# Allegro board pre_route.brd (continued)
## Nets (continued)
DIFF_RX_DRSTAT_N0: J109.10H U7.AH14
DIFF_RX_DRSTAT_N1: J109.9H U7.AH13
DIFF_RX_DRSTAT_P0: J109.10G U7.AG16
DIFF_RX_DRSTAT_P1: J109.9G U7.AH5
DIFF_RX_N<0>: J57.A1 J108.10D U7.Y31
DIFF_RX_N<1>: J57.A2 J108.9H U7.Y29
DIFF_RX_N<2>: J57.A4 J108.9D U7.W32
DIFF_RX_N<3>: J57.A5 J108.10F U7.V31
DIFF_RX_N<4>: J57.A7 J108.10B U7.AJ32
DIFF_RX_N<5>: J57.A8 J108.9F U7.AH32
DIFF_RX_N<6>: J57.A10 J108.8F U7.AH30
DIFF_RX_N<7>: J57.A11 J108.8D U7.AG32
DIFF_RX_N<8>: J57.A15 J108.7F U7.AG30
DIFF_RX_N<9>: J57.A16 J108.8B U7.AF32
DIFF_RX_N<10>: J57.A18 J108.7B U7.AF30
DIFF_RX_N<11>: J57.A19 J108.7H U7.AE32
DIFF_RX_N<12>: J57.A21 J108.6B U7.AE30
DIFF_RX_N<13>: J57.A22 J108.6D U7.AD32
DIFF_RX_N<14>: J57.A24 J108.7D U7.AC32
DIFF_RX_N<15>: J57.A25 J108.6H U7.AB32
DIFF_RX_P<0>: J57.B1 J108.10C U7.Y30
DIFF_RX_P<1>: J57.B2 J108.9G U7.Y28
DIFF_RX_P<2>: J57.B4 J108.9C U7.W31
DIFF_RX_P<3>: J57.B5 J108.10E U7.V30
DIFF_RX_P<4>: J57.B7 J108.10A U7.AJ31
DIFF_RX_P<5>: J57.B8 J108.9E U7.AH31
DIFF_RX_P<6>: J57.B10 J108.8E U7.AH29
DIFF_RX_P<7>: J57.B11 J108.8C U7.AG31
DIFF_RX_P<8>: J57.B15 J108.7E U7.AG29
DIFF_RX_P<9>: J57.B16 J108.8A U7.AF31
DIFF_RX_P<10>: J57.B18 J108.7A U7.AF29
DIFF_RX_P<11>: J57.B19 J108.7G U7.AE31
DIFF_RX_P<12>: J57.B21 J108.6A U7.AE29
DIFF_RX_P<13>: J57.B22 J108.6C U7.AD31
DIFF_RX_P<14>: J57.B24 J108.7C U7.AC31
DIFF_RX_P<15>: J57.B25 J108.6G U7.AB31
DIFF_RX_RCTL_N: J108.6F U7.AB30
DIFF_RX_RCTL_P: J108.6E U7.AB29
DIFF_RX_RDCLK_N: J57.A13 J108.9B R61.1
DIFF_RX_RDCLK_P: J57.B13 J108.9A R61.2
DIFF_RX_RSCLK: J108.8G U7.AM8
DIFF_RX_RSTAT<0>: J108.10H U7.AM7
DIFF_RX_RSTAT<1>: J108.10G U7.AM6
DIFF_TX_DTSCLK_N: J109.5B
DIFF_TX_DTSCLK_P: J109.5A
DIFF_TX_DTSTAT_N0: J109.2D U7.Y11
DIFF_TX_DTSTAT_N1: J109.1D U7.AB12
DIFF_TX_DTSTAT_P0: J109.2C U7.Y10
DIFF_TX_DTSTAT_P1: J109.1C U7.AD10
DIFF_TX_N<0>: J58.A1 J108.2H U7.T28
DIFF_TX_N<1>: J58.A2 J108.1D U7.T23
DIFF_TX_N<2>: J58.A4 J108.1B U7.R29
DIFF_TX_N<3>: J58.A5 J108.1F U7.R27
DIFF_TX_N<4>: J58.A7 J108.3F U7.R25
DIFF_TX_N<5>: J58.A8 J108.1H U7.R23
DIFF_TX_N<6>: J58.A10 J108.3B U7.P29
DIFF_TX_N<7>: J58.A11 J108.2B U7.P27
DIFF_TX_N<8>: J58.A15 J108.4H U7.N27
DIFF_TX_N<9>: J58.A16 J108.2F U7.N25
DIFF_TX_N<10>: J58.A18 J108.4B U7.N23
DIFF_TX_N<11>: J58.A19 J108.4D U7.M27
DIFF_TX_N<12>: J58.A21 J108.4F U7.M25
DIFF_TX_N<13>: J58.A22 J108.5F U7.M23
DIFF_TX_N<14>: J58.A24 J108.3D U7.L26
DIFF_TX_N<15>: J58.A25 J108.5H U7.L24
DIFF_TX_P<0>: J58.B1 J108.2G U7.T27
DIFF_TX_P<1>: J58.B2 J108.1C U7.T22
DIFF_TX_P<2>: J58.B4 J108.1A U7.R28
DIFF_TX_P<3>: J58.B5 J108.1E U7.R26
DIFF_TX_P<4>: J58.B7 J108.3E U7.R24
DIFF_TX_P<5>: J58.B8 J108.1G U7.R22
DIFF_TX_P<6>: J58.B10 J108.3A U7.P28
DIFF_TX_P<7>: J58.B11 J108.2A U7.P26
DIFF_TX_P<8>: J58.B15 J108.4G U7.N26
DIFF_TX_P<9>: J58.B16 J108.2E U7.N24
DIFF_TX_P<10>: J58.B18 J108.4A U7.N22
DIFF_TX_P<11>: J58.B19 J108.4C U7.M26
DIFF_TX_P<12>: J58.B21 J108.4E U7.M24
DIFF_TX_P<13>: J58.B22 J108.5E U7.M22
DIFF_TX_P<14>: J58.B24 J108.3C U7.L25
DIFF_TX_P<15>: J58.B25 J108.5G U7.L23
DIFF_TX_TCTL_N: J108.5D U7.K27
DIFF_TX_TCTL_P: J108.5C U7.K26
DIFF_TX_TDCLK_N: J58.A13 J108.3H U7.P25
DIFF_TX_TDCLK_P: J58.B13 J108.3G U7.P24
DIFF_TX_TSCLK: J108.5A U7.AM9
DIFF_TX_TSTAT<0>: J108.2D U7.AE13
DIFF_TX_TSTAT<1>: J108.2C U7.AB13
DIMM_ODT0: XU2.195
DIVIDE_BY_20_LVPECL_OUT_N: J37.1(OUTPUT) R40.2 R43.1 U6.12(_FWSL_Q3)
DIVIDE_BY_20_LVPECL_OUT_P: J43.1(OUTPUT) R43.2 R48.1 U6.13
DIVIDE_BY_20_LVTTL_OUT: J49.1(OUTPUT) R52.2
DL: U14.6 U17.4
DPA_RX_N<0>: J89.1(OUTPUT) U7.R31
DPA_RX_N<1>: J100.1(OUTPUT) U7.P32
DPA_RX_P<0>: J84.1(OUTPUT) U7.R30
DPA_RX_P<1>: J95.1(OUTPUT) U7.P31
DPA_TX_N<0>: J94.1(OUTPUT) U7.Y27
DPA_TX_N<1>: J102.1(OUTPUT) U7.Y23
DPA_TX_P<0>: J99.1(OUTPUT) U7.Y26
DPA_TX_P<1>: J106.1(OUTPUT) U7.Y22
DPACLK_IN_N: J107.1(OUTPUT)
DPACLK_IN_P: J103.1(OUTPUT)
DPACLK_OUT_N: J88.1(OUTPUT) U7.Y25
DPACLK_OUT_P: J83.1(OUTPUT) U7.Y24
EN_CONFIG_DEV_N: R145.1 U19.29 U20.39 U21.29
EN_PS_MODE_N: R51.1 U19.39
EPC16_TDI: U29.42
EXT_CLK1: J104.1(OUTPUT) R176.2 U32.4
EXT_CLK2: J91.1(OUTPUT) R177.2 U18.4
EXT_CLK_IN_N: J62.1(OUTPUT) R86.2 U10.4
EXT_CLK_IN_P: J61.1(OUTPUT) R86.1 U10.3
FLASH_A<0>: U15.AD31 U29.65 U29.75 U31.25
FLASH_A<1>: U15.AD32 U29.56 U29.62 U31.24
FLASH_A<2>: U15.AC31 U29.55 U31.23
FLASH_A<3>: U15.AB32 U29.54 U31.22
FLASH_A<4>: U15.AB26 U29.53 U31.21
FLASH_A<5>: U15.AA24 U29.52 U31.20
FLASH_A<6>: U15.AG29 U29.51 U31.19
FLASH_A<7>: U15.AG30 U29.50 U31.18
FLASH_A<8>: U15.AG32 U29.34 U31.8
FLASH_A<9>: U15.AG31 U29.32 U31.7
FLASH_A<10>: U15.AF29 U29.31 U31.6
FLASH_A<11>: U15.AF30 U29.29 U31.5
FLASH_A<12>: U15.AF31 U29.28 U31.4
FLASH_A<13>: U15.AF32 U29.27 U31.3
FLASH_A<14>: U15.AE29 U29.26 U31.2
FLASH_A<15>: U15.AE30 U29.21 U29.25 U31.1
FLASH_A<16>: U15.AE31 U29.6 U29.17 U31.48
FLASH_A<17>: U15.AE32 U29.49 U31.17
FLASH_A<18>: U15.AD29 U29.47 U31.16
FLASH_A<19>: U15.AD30 U29.46 U31.9
FLASH_A<20>: U15.AC30 U29.36 U31.10
FLASH_A<21>: U15.AC29 U31.13
FLASH_BYTEN: R233.1 U15.Y24 U31.47
FLASH_CEN: R231.1 U15.AA26 U31.26
FLASH_D<0>: U15.AF25 U29.81 U31.29
FLASH_D<1>: U15.AF26 U29.83 U31.31
FLASH_D<2>: U15.AF28 U29.86 U31.33
FLASH_D<3>: U15.AF27 U29.89 U31.35
FLASH_D<4>: U15.AE26 U29.93 U31.38
FLASH_D<5>: U15.AE25 U29.95 U31.40
FLASH_D<6>: U15.AE27 U29.98 U31.42
FLASH_D<7>: U15.AE28 U29.100 U31.44
FLASH_D<8>: U15.AD25 U29.82 U31.30
FLASH_D<9>: U15.AD26 U29.85 U31.32
FLASH_D<10>: U15.AD27 U29.87 U31.34
FLASH_D<11>: U15.AD28 U29.90 U31.36
FLASH_D<12>: U15.AC28 U29.94 U31.39
FLASH_D<13>: U15.AC27 U29.97 U31.41
FLASH_D<14>: U15.AC26 U29.99 U31.43
FLASH_D<15>: U15.AC25 U29.1 U31.45
FLASH_OEN: R232.1 U15.AB27 U31.28
FLASH_RDY_BSYN: R360.2 U31.15
FLASH_RESETN: R280.1 U15.AA25 U31.12
FLASH_WEN: R281.1 U15.AA27 U31.11
FLASH_WPN: R279.1 U31.14(WP_ACC)
GLOBAL_RST_LED: RN22.3 U34.19
GLOBAL_RST_N: R149.1 RN20.14 U19.26 U19.36 U21.26 U34.30 U43.15
GLOBAL_RST_N_IN: C657.1 R149.2 R175.1 U43.1
GX_A_A: RN36.1 U25.12
GX_A_B: RN35.1 U25.23
GX_ALERTN: U5.11 U15.L14
GX_B_A: RN36.2 U25.11
GX_B_B: RN35.2 U25.22
GX_C_A: RN36.3 U25.9
GX_C_B: RN35.3 U25.20
GX_CDONE_BUF_N: R144.1 R179.1 U19.37 U21.27
GX_CDONE_N: U19.3
GX_CONFIG_BUF_N: R42.1
GX_D_A: RN36.4 U25.8
GX_D_B: RN35.4 U25.19
GX_DATA0: U19.34 U21.24
GX_DATA1: U21.23
GX_DATA2: U21.22
GX_DATA3: U21.21
GX_DATA4: U20.34
GX_DATA5: U20.33
GX_DATA6: U20.32
GX_DATA7: U20.31
GX_DCLK_BUF: R142.1 U21.28
GX_DEV_CLR_LED: RN22.1 U34.22
GX_DIG_1_A: RN15.16 U7.AJ8 U25.37
GX_DIG_1_B: RN15.15 U7.AK10 U25.38
GX_DIG_1_C: RN15.14 U7.AK11 U25.40
GX_DIG_1_D: RN15.13 U7.AK12 U25.41
GX_DIG_1_DP: RN15.9(2) U7.AK6 U25.47
GX_DIG_1_E: RN15.12 U7.AK13 U25.43
GX_DIG_1_F: RN15.11 U7.AK4 U25.44
GX_DIG_1_G: RN15.10 U7.AK5 U25.46
GX_DIG_2_A: RN16.16 U7.AJ10 U25.26
GX_DIG_2_B: RN16.15 U7.AJ11 U25.27
GX_DIG_2_C: RN16.14 U7.AJ12 U25.29
GX_DIG_2_D: RN16.13 U7.AJ13 U25.30
GX_DIG_2_DP: RN16.9(2) U7.AJ7 U25.36
GX_DIG_2_E: RN16.12 U7.AJ14 U25.32
GX_DIG_2_F: RN16.11 U7.AJ5 U25.33
GX_DIG_2_G: RN16.10 U7.AJ6 U25.35
GX_DIP<0>: RN37.14 U7.AJ21
GX_DIP<1>: RN37.13 U7.AJ20
GX_DIP<2>: RN37.12 U7.AJ19
GX_DIP<3>: RN37.11 U7.AH28
GX_DIP<4>: RN37.9(2) U7.AH26
GX_DIP<5>: RN38.15 U7.AH25
GX_DIP<6>: RN38.13 U7.AH24
GX_DIP<7>: RN38.11 U7.AH22
GX_DP_A: RN36.8 U25.2
GX_DP_B: RN35.8 U25.13
GX_E_A: RN36.5 U25.6
GX_E_B: RN35.5 U25.17
GX_EPC16_CEN: U15.AE13 U30.78
GX_EPC16_OEN: U15.AC13 U30.80
GX_EPC16_RPN: U15.AG12 U30.39 U30.72
GX_EPC16_WEN: U15.AD13 U30.33 U30.38
GX_F_A: RN36.6 U25.5
GX_F_B: RN35.6 U25.16
GX_FLASH_A<0>: U15.AK4 U30.65 U30.75
GX_FLASH_A<1>: U15.AK3 U30.56 U30.62
GX_FLASH_A<2>: U15.AH5 U30.55
GX_FLASH_A<3>: U15.AJ5 U30.54
GX_FLASH_A<4>: U15.AJ4 U30.53
GX_FLASH_A<5>: U15.AM4 U30.52
GX_FLASH_A<6>: U15.AL4 U30.51
GX_FLASH_A<7>: U15.AL3 U30.50
GX_FLASH_A<8>: U15.AJ6 U30.34
GX_FLASH_A<9>: U15.AK6 U30.32
GX_FLASH_A<10>: U15.AL5 U30.31
GX_FLASH_A<11>: U15.AK7 U30.29
GX_FLASH_A<12>: U15.AM5 U30.28
GX_FLASH_A<13>: U15.AJ7 U30.27
GX_FLASH_A<14>: U15.AM6 U30.26
GX_FLASH_A<15>: U15.AL6 U30.21 U30.25
GX_FLASH_A<16>: U15.AL7 U30.6 U30.17
GX_FLASH_A<17>: U15.AJ8 U30.49
GX_FLASH_A<18>: U15.AM7 U30.47
GX_FLASH_A<19>: U15.AH9 U30.46
GX_FLASH_A<20>: U15.AM8 U30.36
GX_FLASH_D<0>: U15.AE12 U30.81
GX_FLASH_D<1>: U15.AC12 U30.83
GX_FLASH_D<2>: U15.AA12 U30.86
GX_FLASH_D<3>: U15.AD12 U30.89
GX_FLASH_D<4>: U15.AB11 U30.93
GX_FLASH_D<5>: U15.AE11 U30.95
GX_FLASH_D<6>: U15.AF10 U30.98
GX_FLASH_D<7>: U15.AG10 U30.100
GX_FLASH_D<8>: U15.AG11 U30.82
GX_FLASH_D<9>: U15.AD9 U30.85
GX_FLASH_D<10>: U15.AG9 U30.87
GX_FLASH_D<11>: U15.AC9 U30.90
GX_FLASH_D<12>: U15.AE9 U30.94
GX_FLASH_D<13>: U15.AF9 U30.97
GX_FLASH_D<14>: U15.AD14 U30.99
GX_FLASH_D<15>: U15.AB13 U30.1
GX_G_A: RN36.7 U25.3
GX_G_B: RN35.7 U25.14
GX_HEADER<0>: J53.1 U7.AM5
GX_HEADER<1>: J53.3 U7.AM4
GX_HEADER<2>: J53.5 U7.AM14
GX_HEADER<3>: J53.7 U7.AM12
GX_HEADER<4>: J53.9 U7.AM11
GX_HEADER<5>: J53.11 U7.AM10
GX_HEADER<6>: J53.13 U7.AL9
GX_HEADER<7>: J53.15 U7.AL8
GX_HEADER<8>: J53.17 U7.AL7
GX_HEADER<9>: J53.19 U7.AL6
GX_HEADER<10>: J53.20 U7.AL5
GX_HEADER<11>: J53.18 U7.AL4
GX_HEADER<12>: J53.16 U7.AL14
GX_HEADER<13>: J53.14 U7.AL13
GX_HEADER<14>: J53.12 U7.AL12
GX_HEADER<15>: J53.10 U7.AL11
GX_HEADER<16>: J53.8 U7.AL10
GX_HEADER<17>: J53.6 U7.AK9
GX_HEADER<18>: J53.4 U7.AK8
GX_HEADER<19>: J53.2 U7.AK7
GX_LED<0>: RN19.15 U7.AC16 U34.38
GX_LED<1>: RN19.16 U7.AC15 U34.37
GX_LED<2>: RN20.10 U7.AC14 U34.36
GX_LED<3>: RN20.11 U7.AC12 U34.35
GX_LED<4>: RN20.12 U7.AB16 U34.33
GX_LED<5>: RN20.13 U7.AB14 U34.32
GX_MICTOR_EP_<0>: J34.37 U7.AM28
GX_MICTOR_EP_<1>: J34.35 U7.AM27
GX_MICTOR_EP_<2>: J34.33 U7.AM26
GX_MICTOR_EP_<3>: J34.31 U7.AM25
GX_MICTOR_EP_<4>: J34.29 U7.AM24
GX_MICTOR_EP_<5>: J34.27 U7.AM23
GX_MICTOR_EP_<6>: J34.25 U7.AM22
GX_MICTOR_EP_<7>: J34.23 U7.AM21
GX_MICTOR_EP_<8>: J34.21 U7.AL29
GX_MICTOR_EP_<9>: J34.19 U7.AL28
GX_MICTOR_EP_<10>: J34.17 U7.AL27
GX_MICTOR_EP_<11>: J34.15 U7.AL26
GX_MICTOR_EP_<12>: J34.13 U7.AL25
GX_MICTOR_EP_<13>: J34.11 U7.AL24
GX_MICTOR_EP_<14>: J34.9 U7.AL23
GX_MICTOR_EP_<15>: J34.7 U7.AL22
GX_MICTOR_EP_CLK: J34.5 U7.AM29
GX_MICTOR_OP_<0>: J34.38 U7.AL20
GX_MICTOR_OP_<1>: J34.36 U7.AK29
GX_MICTOR_OP_<2>: J34.34 U7.AK28
GX_MICTOR_OP_<3>: J34.32 U7.AK27
GX_MICTOR_OP_<4>: J34.30 U7.AK26
GX_MICTOR_OP_<5>: J34.28 U7.AK25
GX_MICTOR_OP_<6>: J34.26 U7.AK24
GX_MICTOR_OP_<7>: J34.24 U7.AK23
GX_MICTOR_OP_<8>: J34.22 U7.AK22
GX_MICTOR_OP_<9>: J34.20 U7.AK21
GX_MICTOR_OP_<10>: J34.18 U7.AK20
GX_MICTOR_OP_<11>: J34.16 U7.AJ28
GX_MICTOR_OP_<12>: J34.14 U7.AJ27
GX_MICTOR_OP_<13>: J34.12 U7.AJ26
GX_MICTOR_OP_<14>: J34.10 U7.AJ25
GX_MICTOR_OP_<15>: J34.8 U7.AJ23
GX_MICTOR_OP_CLK: J34.6 U7.AL21
GX_OVERTEMPN: U5.9 U15.F13
GX_PB0_IN: C648.1 R186.2 RN14.15 U44.14
GX_PB1_IN: C649.1 R203.2 RN14.14 U44.3
GX_PB2_IN: C650.1 R208.2 RN14.12 U44.12
GX_PB3_IN: C658.1 R212.2 RN14.10 U44.5
GX_PB<0>: R186.1 U7.AD14 U44.2
GX_PB<1>: R203.1 U7.AD13 U44.13
GX_PB<2>: R208.1 U7.AD12 U44.4
GX_PB<3>: R212.1 U7.AD11 U44.11
GX_PB_DEV_CLR_N: R184.1 U34.27 U44.15
GX_PB_DEV_CLR_N_IN: C647.1 R184.2 RN14.16 U44.1
GX_PGM0: U21.6
GX_PGM1: U21.7
GX_PGM2: U21.8
GX_PLL_ENA: R57.1
GX_RECOV_CLK<0>: J5.1(OUTPUT) U7.AB17
GX_RECOV_CLK<1>: J4.1(OUTPUT) U7.AC20
GX_RECOV_CLK<2>: J2.1(OUTPUT) U7.AD23
GX_RECOV_CLK<3>: J3.1(OUTPUT) U7.AF21
GX_RECOV_CLK<4>: J6.1(OUTPUT) U7.AJ22
GX_RS232_CTS: R163.2 U7.AE11 U28.9
GX_RS232_RTS: R164.2 U7.AE14 U28.10
GX_RS232_RXD: U7.AE12 U28.12
GX_RS232_TXD: U7.AB15 U28.11
GX_RUNLU: R37.1 U20.24 U21.31
GX_RX1IN1: J124.12 U28.13
GX_RX2IN1: J124.16 U28.8
GX_SMB_CLK: U5.14 U15.H13
GX_SMB_DATA: U5.12 U15.C14
GX_STATUS_BUF_N: R143.1 U19.35 U21.25
GX_TEMPDIODEN: U5.4
GX_TEMPDIODEP: U5.3
GX_TX1OUT1: J124.11(TXD) U28.14
GX_TX2OUT1: J124.17 U28.7
GX_USER_LED1: RN21.2 U34.11
GX_USER_LED2: RN21.1 U34.12
GX_USER_LED3: RN22.7 U34.13
GX_USER_LED4: RN22.6 U34.14
GX_USER_LED5: RN22.5 U34.16
GX_USER_LED6: RN22.4 U34.17
GX_VCCSEL: R39.1
GXPGM<0>: R289.1 U20.23 U21.34 U30.14
GXPGM<1>: R290.1 U20.22 U21.33 U30.13
GXPGM<2>: R291.1 U20.21 U21.32 U30.15
HIDRV: R62.1 U37.12
LAN_A<0>: U11.78 U15.H30
LAN_A<1>: U11.79 U15.G30
LAN_A<2>: U11.80 U15.R29
LAN_A<3>: U11.81 U15.R30
LAN_A<4>: U11.82 U15.R31
LAN_A<5>: U11.83 U15.R32
LAN_A<6>: U11.84 U15.P32
LAN_A<7>: U11.85 U15.P31
LAN_A<8>: U11.86 U15.P30
LAN_A<9>: U11.87 U15.P29
LAN_A<10>: U11.88 U15.N32
LAN_A<11>: U11.89 U15.N31
LAN_A<12>: U11.90 U15.N30
LAN_A<13>: U11.91 U15.N29
LAN_A<14>: U11.92 U15.M30
LAN_ADSN: R125.1 U11.37
LAN_AEN: U11.41 U15.M29
LAN_BEN<0>: U11.94 U15.K30
LAN_BEN<1>: U11.95 U15.J30
LAN_BEN<2>: U11.96 U15.J29
LAN_BEN<3>: U11.97 U15.H32
LAN_CYCLEN: U11.35
LAN_D<0>: U11.107 U15.J26
LAN_D<1>: U11.106 U15.J25
LAN_D<2>: U11.105 U15.H26
LAN_D<3>: U11.104 U15.H25
LAN_D<4>: U11.102 U15.J28
LAN_D<5>: U11.101 U15.J27
LAN_D<6>: U11.100 U15.R24
LAN_D<7>: U11.99 U15.R23
LAN_D<8>: U11.76 U15.P26
LAN_D<9>: U11.75 U15.P25
LAN_D<10>: U11.74 U15.R27
LAN_D<11>: U11.73 U15.R28
LAN_D<12>: U11.71 U15.P27
LAN_D<13>: U11.70 U15.P28
LAN_D<14>: U11.69 U15.N26
LAN_D<15>: U11.68 U15.N25
LAN_D<16>: U11.66 U15.P24
LAN_D<17>: U11.65 U15.P23
LAN_D<18>: U11.64 U15.N28
LAN_D<19>: U11.63 U15.N27
LAN_D<20>: U11.61 U15.N23
LAN_D<21>: U11.60 U15.N24
LAN_D<22>: U11.59 U15.M25
LAN_D<23>: U11.58 U15.M24
LAN_D<24>: U11.56 U15.M27
LAN_D<25>: U11.55 U15.M26
LAN_D<26>: U11.54 U15.L26
LAN_D<27>: U11.53 U15.L27
LAN_D<28>: U11.51 U15.K25
LAN_D<29>: U11.50 U15.K26
LAN_D<30>: U11.49 U15.K27
LAN_D<31>: U11.48 U15.K28
LAN_DATACS_N: U11.34 U15.G31
LAN_ENEEP: R242.1 U11.6
LAN_INTRQ0: U11.29 U15.L30
LAN_IOCHRDY: U11.38 U15.K31
LAN_IORN: R121.1 U11.31 U15.M28
LAN_IOWN: U11.32 U15.L32
LAN_LCLK: R128.1 U11.42
LAN_LDEVN: U11.45 U15.J31
LAN_LEDA_N: RJ1.10 U11.22
LAN_LEDB_N: RJ1.12 U11.23
LAN_LOOPBACK: U11.21 U15.J32
LAN_OSC_EN: Y4.1
LAN_RBIAS: R102.1 U11.12
LAN_RDYRTNN: U11.46
LAN_RESET: U11.30 U15.L31
LAN_RXDN: R118.2 RJ1.6
LAN_RXDP: R103.2 RJ1.4
LAN_SRDY_N: U11.43 U15.G32
LAN_TXDN: R244.1 RJ1.3 U11.15
LAN_TXDP: R243.1 RJ1.1(TDP) U11.14
LAN_VLBUS_N: U11.40 U15.H29
LAN_W_RN: U11.36
LODRV: R71.1 U37.9
MAIN_PWR: ISO1.1
MAIN_SWN: J31.14
MSEL0: R53.1 U15.AG18
MSEL1: R68.1 U15.AE18
MSEL2: R130.1 U15.AE19
NET_2_I2_1: C727.1
NET_2_I12_2: C418.2 R222.1 R223.2 U38.4
NET_2_I17_1: C731.1
NET_2_I21_2: C313.1 U37.6 U37.7
NET_2_I22_2: C328.1 R215.2 U37.3
NET_2_I25_G: R62.2
NET_2_I31_2: R350.2 R351.2 U8.6
NET_2_I32_1: C307.1 U37.1
NET_2_I38_G: R71.2
NET_2_I41_1: C729.1
NET_2_I48_TP: J31.8
NET_2_I52_2: C725.2 R344.2 U38.1 U38.2
NET_2_I70_VREF: C308.1 U37.20(VREF)
NET_2_I149_IN: C732.1
NET_2_I150_IN: C730.1
NET_3_I14_ADJ: R3.2 R4.2 U1.5
NET_3_I15_2: C167.1 U36.6 U36.7
NET_3_I17_IN: C733.1
NET_3_I19_2: C726.1 R185.1 R187.2 U36.16
NET_3_I22_1: C735.1
NET_3_I22_2: C736.1
NET_3_I27_1: C134.1 U36.20(VREF)
NET_3_I33_CEXT: C133.1 U36.1
NET_3_I33_HIDRV: R202.1 U36.12
NET_3_I33_LODRV: R190.1 U36.9
NET_3_I33_VCCQP: C232.1 R301.2 U36.13
NET_3_I34_1: C42.1 C238.1 C239.1
NET_3_I37_2: C734.1
NET_3_I41_2: R202.2
NET_3_I46_2: R190.2
NET_3_I121_2: C147.1 R189.2 U36.3
NET_4_I14_2: R5.2 R6.2 U2.1
NET_4_I17_1: C718.1 R324.2
NET_4_I18_1: C700.1 R327.1 U53.8(VTT)
NET_4_I18_2: R327.2 R329.2 U53.3
NET_4_I48_1: C715.1
NET_5_I2_Q1: U46.6
NET_5_I20_Q0: J80.1(OUTPUT) U47.7
NET_5_I20_Q1: U47.6
NET_6_I12_1: J76.1(OUTPUT) R126.1
NET_6_I12_2: R126.2 R127.2 U13.3
NET_6_I15_2: R28.1 R32.2 U6.3
NET_6_I16_2: R47.2 R214.1 U6.15 U9.2
NET_6_I17_1: R52.1 U9.7
NET_6_I19_OUTPUT: J46.1(OUTPUT) U10.26
NET_6_I20_2: R46.2 R214.2 U6.14 U9.3(_FWSL_D)
NET_6_I21_1: C790.1 R361.1 U60.1 U60.3
NET_6_I25_D: C31.2 R18.2 R19.1 U4.2
NET_6_I25_FWSLD: C30.2 R17.2 R18.1 U4.3(_FWSL_D)
NET_6_I25_Q0: R33.2 R35.2 U4.7 U6.4
NET_6_I25_Q1: R27.2 R33.1 U4.6 U6.5
NET_6_I25_RST: R21.2 U4.1
NET_6_I26_2: R31.1 R34.2 U6.9
NET_6_I33_ADJ: C775.2 R354.1 R357.1 U60.4
NET_6_I43_VCC: C659.2 C777.1 R355.1 U9.8
NET_6_I48_1: R260.1 Y1.1
NET_6_I80_1: R127.1 Y1.3
NET_7_I12_BASE: R179.2
NET_7_I12_EMITTER: R141.1
NET_7_I14_7: J48.2
NET_7_I19_DATA0: R277.1 U29.73
NET_7_I19_DATA1: R275.1 U29.84
NET_7_I19_DATA2: R272.1 U29.88
NET_7_I19_DATA3: R273.1 U29.91
NET_7_I19_DATA4: R150.1 U29.96
NET_7_I19_DATA5: R151.1 U29.10
NET_7_I19_DATA6: R152.1 U29.9
NET_7_I19_DATA7: R153.1 U29.8
NET_7_I19_PORSEL: R278.2 U29.66
NET_7_I52_1: R139.1
NET_7_I77_1: R178.1
NET_8_I16_1: R154.1 U30.96
NET_8_I17_1: R274.1 U30.84
NET_8_I20_1: R271.1 U30.91
NET_8_I25_DATA0: R276.1 U30.73
NET_8_I25_DATA2: R270.1 U30.88
NET_8_I25_DATA5: R155.1 U30.10
NET_8_I25_DATA6: R156.1 U30.9
NET_8_I25_DATA7: R157.1 U30.8
NET_9_I26_1: PMCJN2.2(TRSTN) R98.1
NET_14_I26_1: C81.1 R117.1
NET_14_I36_2: R247.2 R248.2 U14.3
NET_14_I103_D1A: C92.2 U14.9 U17.1(S2) U17.5 U17.6
NET_20_I1_2: C280.1 R204.2 U5.1(VCC) U5.15
NET_22_I11_1: C90.1 R124.2 U12.1(VCC) U12.15
NET_22_I15_PLL6OUT0P: R349.1 U15.AL16
NET_23_I13_1: C638.1 R261.1
NET_27_I13_1: C703.1 U44.7
NET_27_I13_2: C703.2 U44.9
NET_27_I21_OSCIN: C702.1 U43.7
NET_27_I21_OSCOUT: C702.2 U43.9
NET_28_I4_1: C113.1 U28.1
NET_28_I4_2: C113.2 U28.3
NET_28_I10_1: C116.1 U33.6
NET_28_I11_1: C112.1 U28.5
NET_28_I11_2: C112.2 U28.4
NET_28_I12_DCE: J124.10 J124.13 J124.15
NET_28_I14_1: C118.1 U33.1
NET_28_I14_2: C118.2 U33.3
NET_28_I15_1: C111.1 U28.6
NET_28_I16_1: C119.1 U33.2
NET_28_I17_1: C117.1 U33.5
NET_28_I17_2: C117.2 U33.4
NET_28_I18_1: C114.1 U28.2
NET_29_I15_2: RN34.10
NET_30_I1_2: RN21.9(2)
NET_30_I10_2: RN22.12
NET_30_I12_2: R285.2 U34.1
NET_30_I13_2: R283.2 U34.48
NET_30_I14_2: RN21.10
NET_30_I16_2: R282.2 U34.25
NET_30_I20_CATHODE: RN21.13
NET_30_I21_CATHODE: RN22.15
NET_30_I22_2: RN22.16
NET_30_I24_CATHODE: RN21.12
NET_30_I25_CATHODE: RN21.14
NET_30_I26_CATHODE: RN22.13
NET_30_I31_2: RN22.11
NET_30_I33_CATHODE: RN21.11
NET_30_I35_2: RN21.16
NET_30_I38_2: R284.2 U34.24
NET_30_I39_2: RN22.10
NET_30_I40_2: RN22.14
NET_30_I43_CATHODE: RN21.15
NET_42_I1_1: C774.1 R352.2 U59.6
NET_42_I14_1: R353.1 U59.1
NIO_PULLUP: U15.AF15
PARALLELBUS_ADDR<0>: RN27.5 U7.K20 XU2.188
PARALLELBUS_ADDR<1>: RN27.7 U7.L19 XU2.183
PARALLELBUS_ADDR<2>: RN27.6 U7.K19 XU2.63
PARALLELBUS_ADDR<3>: RN29.1 U7.J19 XU2.182
PARALLELBUS_ADDR<4>: RN29.2 U7.L18 XU2.61
PARALLELBUS_ADDR<5>: RN29.3 U7.K18 XU2.60
PARALLELBUS_ADDR<6>: RN29.4 U7.L15 XU2.180
PARALLELBUS_ADDR<7>: RN29.6 U7.J14 XU2.58
PARALLELBUS_ADDR<8>: RN29.5 U7.K14 XU2.179
PARALLELBUS_ADDR<9>: RN29.8 U7.L14 XU2.177
PARALLELBUS_ADDR<10>: RN27.3 U7.K21 XU2.70
PARALLELBUS_ADDR<11>: RN29.7 U7.H11 XU2.57
PARALLELBUS_ADDR<12>: R136.2 U7.H14 XU2.176
PARALLELBUS_ADDR<13>: RN27.1 U7.L20 XU2.196
PARALLELBUS_ADDR<14>: RN5.8 U7.H13 XU2.174
PARALLELBUS_ADDR<15>: R1.2 U7.J11 XU2.173
PARALLELBUS_BA<0>: RN27.2 U7.G20 XU2.71
PARALLELBUS_BA<1>: RN27.4 U7.J20 XU2.190
PARALLELBUS_BA<2>: U7.K13 XU2.54
PARALLELBUS_CAS_N: RN5.3 XU2.74
PARALLELBUS_CASN: U7.H22
PARALLELBUS_CB<0>: U7.E13 XU2.42
PARALLELBUS_CB<1>: U7.D13 XU2.43
PARALLELBUS_CB<2>: U7.D14 XU2.48
PARALLELBUS_CB<3>: U7.F15 XU2.49
PARALLELBUS_CB<4>: U7.G13 XU2.161
PARALLELBUS_CB<5>: U7.F13 XU2.162
PARALLELBUS_CB<6>: U7.A14 XU2.167
PARALLELBUS_CB<7>: U7.B14 XU2.168
PARALLELBUS_CLK0_N: U7.C15 XU2.186
PARALLELBUS_CLK0_P: U7.B15 XU2.185
PARALLELBUS_CLK1_N: U7.D16 XU2.138
PARALLELBUS_CLK1_P: U7.C16 XU2.137
PARALLELBUS_CLK2_N: U7.E15 XU2.221
PARALLELBUS_CLK2_P: U7.D15 XU2.220
PARALLELBUS_CLK_EN<0>: R76.2 RN5.4 U7.L13 XU2.52
PARALLELBUS_CLK_EN<1>: R77.2 RN5.5 U7.K12 XU2.171
PARALLELBUS_CS0_N: RN5.6 U7.J21 XU2.76
PARALLELBUS_CS1_N: RN5.7 U7.K22
PARALLELBUS_CSN0: XU2.193
PARALLELBUS_DATA<0>: RN32.14 U7.D6 XU2.3
PARALLELBUS_DATA<1>: RN32.13 U7.D5 XU2.4
PARALLELBUS_DATA<2>: RN32.10 U7.A4 XU2.9
PARALLELBUS_DATA<3>: RN32.9(2) U7.A5 XU2.10
PARALLELBUS_DATA<4>: RN32.16 U7.E5 XU2.122
PARALLELBUS_DATA<5>: RN32.15 U7.C6 XU2.123
PARALLELBUS_DATA<6>: RN32.12 U7.B4 XU2.128
PARALLELBUS_DATA<7>: RN32.11 U7.A6 XU2.129
PARALLELBUS_DATA<8>: RN31.14 U7.E6 XU2.12
PARALLELBUS_DATA<9>: RN31.13 U7.A7 XU2.13
PARALLELBUS_DATA<10>: RN31.10 U7.A8 XU2.21
PARALLELBUS_DATA<11>: RN31.9(2) U7.C9 XU2.22
PARALLELBUS_DATA<12>: RN31.16 U7.E7 XU2.131
PARALLELBUS_DATA<13>: RN31.15 U7.B7 XU2.132
PARALLELBUS_DATA<14>: RN31.12 U7.C8 XU2.140
PARALLELBUS_DATA<15>: RN31.11 U7.A9 XU2.141
PARALLELBUS_DATA<16>: RN30.14 U7.F8 XU2.24
PARALLELBUS_DATA<17>: RN30.13 U7.F10 XU2.25
PARALLELBUS_DATA<18>: RN30.10 U7.B10 XU2.30
PARALLELBUS_DATA<19>: RN30.9(2) U7.D10 XU2.31
PARALLELBUS_DATA<20>: RN30.16 U7.E8 XU2.143
PARALLELBUS_DATA<21>: RN30.15 U7.D8 XU2.144
PARALLELBUS_DATA<22>: RN30.12 U7.D11 XU2.149
PARALLELBUS_DATA<23>: RN30.11 U7.A10 XU2.150
PARALLELBUS_DATA<24>: RN28.14 U7.G11 XU2.33
PARALLELBUS_DATA<25>: RN28.13 U7.A11 XU2.34
PARALLELBUS_DATA<26>: RN28.10 U7.E11 XU2.39
PARALLELBUS_DATA<27>: RN28.9(2) U7.D12 XU2.40
PARALLELBUS_DATA<28>: RN28.16 U7.G10 XU2.152
PARALLELBUS_DATA<29>: RN28.15 U7.B11 XU2.153
PARALLELBUS_DATA<30>: RN28.12 U7.A12 XU2.158
PARALLELBUS_DATA<31>: RN28.11 U7.G12 XU2.159
PARALLELBUS_DATA<32>: RN26.14 U7.C20 XU2.80
PARALLELBUS_DATA<33>: RN26.13 U7.B20 XU2.81
PARALLELBUS_DATA<34>: RN26.10 U7.A22 XU2.86
PARALLELBUS_DATA<35>: RN26.9(2) U7.C22 XU2.87
PARALLELBUS_DATA<36>: RN26.16 U7.E19 XU2.199
PARALLELBUS_DATA<37>: RN26.15 U7.E20 XU2.200
PARALLELBUS_DATA<38>: RN26.12 U7.C21 XU2.205
PARALLELBUS_DATA<39>: RN26.11 U7.A21 XU2.206
PARALLELBUS_DATA<40>: RN25.14 U7.A23 XU2.89
PARALLELBUS_DATA<41>: RN25.13 U7.C23 XU2.90
PARALLELBUS_DATA<42>: RN25.10 U7.D23 XU2.95
PARALLELBUS_DATA<43>: RN25.9(2) U7.F23 XU2.96
PARALLELBUS_DATA<44>: RN25.16 U7.F22 XU2.208
PARALLELBUS_DATA<45>: RN25.15 U7.D21 XU2.209
PARALLELBUS_DATA<46>: RN25.12 U7.C24 XU2.214
PARALLELBUS_DATA<47>: RN25.11 U7.A24 XU2.215
PARALLELBUS_DATA<48>: RN24.14 U7.A26 XU2.98
PARALLELBUS_DATA<49>: RN24.13 U7.C25 XU2.99
PARALLELBUS_DATA<50>: RN24.10 U7.E26 XU2.107
PARALLELBUS_DATA<51>: RN24.9(2) U7.E27 XU2.108
PARALLELBUS_DATA<52>: RN24.16 U7.E24 XU2.217
PARALLELBUS_DATA<53>: RN24.15 U7.A25 XU2.218
PARALLELBUS_DATA<54>: RN24.12 U7.D26 XU2.226
PARALLELBUS_DATA<55>: RN24.11 U7.C26 XU2.227
PARALLELBUS_DATA<56>: RN23.14 U7.A29 XU2.110
PARALLELBUS_DATA<57>: RN23.13 U7.C27 XU2.111
PARALLELBUS_DATA<58>: RN23.10 U7.D28 XU2.116
PARALLELBUS_DATA<59>: RN23.9(2) U7.E28 XU2.117
PARALLELBUS_DATA<60>: RN23.16 U7.A27 XU2.229
PARALLELBUS_DATA<61>: RN23.15 U7.A28 XU2.230
PARALLELBUS_DATA<62>: RN23.12 U7.B29 XU2.235
PARALLELBUS_DATA<63>: RN23.11 U7.D27 XU2.236
PARALLELBUS_DM<0>: U7.B5 XU2.125
PARALLELBUS_DM<1>: U7.B8 XU2.134
PARALLELBUS_DM<2>: U7.C10 XU2.146
PARALLELBUS_DM<3>: U7.C12 XU2.155
PARALLELBUS_DM<4>: U7.B21 XU2.202
PARALLELBUS_DM<5>: U7.B23 XU2.211
PARALLELBUS_DM<6>: U7.D25 XU2.223
PARALLELBUS_DM<7>: U7.C28 XU2.232
PARALLELBUS_DM<8>: U7.C13 XU2.164
PARALLELBUS_ODT<0>: U7.E25
PARALLELBUS_ODT<1>: U7.L21 XU2.77
PARALLELBUS_RAS_N: RN5.2 U7.G21
PARALLELBUS_RASN: XU2.192
PARALLELBUS_REF_CLK_SMA: U7.E16
PARALLELBUS_RESET_N: U7.E22 XU2.18
PARALLELBUS_SCL: U7.B28 XU2.120
PARALLELBUS_SDA: U7.J22 XU2.119
PARALLELBUS_STROBE<0>: R238.1 U7.C4 XU2.7
PARALLELBUS_STROBE<1>: R236.1 U7.D7 XU2.16
PARALLELBUS_STROBE<2>: R73.1 U7.F9 XU2.28
PARALLELBUS_STROBE<3>: R70.1 U7.F11 XU2.37
PARALLELBUS_STROBE<4>: R30.1 U7.D19 XU2.84
PARALLELBUS_STROBE<5>: R23.1 U7.D22 XU2.93
PARALLELBUS_STROBE<6>: R11.1 U7.B25 XU2.105
PARALLELBUS_STROBE<7>: R7.1 U7.B27 XU2.114
PARALLELBUS_SYNC_CLK: U7.B13 U7.T30
PARALLELBUS_WE_N: RN5.1 U7.G22 XU2.73
PGM_DIP: R146.1 U20.29
PGM_REMOTE: R147.1 U21.39
PMC_AD<0>: PMCJN1.61 U15.H22
PMC_AD<1>: PMCJN1.60 U15.E22
PMC_AD<2>: PMCJN1.59 U15.D22
PMC_AD<3>: PMCJN1.58 U15.C22
PMC_AD<4>: PMCJN1.55 U15.B22
PMC_AD<5>: PMCJN1.54 U15.A22
PMC_AD<6>: PMCJN1.53 U15.L23
PMC_AD<7>: PMCJN2.51 U15.K23
PMC_AD<8>: PMCJN2.49 U15.H23
PMC_AD<9>: PMCJN1.49 U15.G23
PMC_AD<10>: PMCJN2.48 U15.F23
PMC_AD<11>: PMCJN1.48 U15.D23
PMC_AD<12>: PMCJN1.47 U15.C23
PMC_AD<13>: PMCJN2.46 U15.L24
PMC_AD<14>: PMCJN2.45 U15.K24
PMC_AD<15>: PMCJN1.46 U15.J24
PMC_AD<16>: PMCJN2.25 PMCJN2.31 U15.A25
PMC_AD<17>: PMCJN1.32 U15.B27 U15.F26
PMC_AD<18>: PMCJN2.29 U15.E26
PMC_AD<19>: PMCJN1.29 U15.D26
PMC_AD<20>: PMCJN2.28 U15.C26
PMC_AD<21>: PMCJN1.28 U15.B26
PMC_AD<22>: PMCJN1.27 U15.D27
PMC_AD<23>: PMCJN2.26 U15.C27
PMC_AD<24>: PMCJN2.23 U15.E28
PMC_AD<25>: PMCJN1.23 U15.D28
PMC_AD<26>: PMCJN2.22 U15.C28
PMC_AD<27>: PMCJN1.22 U15.B28
PMC_AD<28>: PMCJN1.21 U15.A28
PMC_AD<29>: PMCJN2.20 U15.D29
PMC_AD<30>: PMCJN2.19 U15.C29
PMC_AD<31>: PMCJN1.20 U15.B29
PMC_BUSMODEN<1>: PMCJN1.7 U15.L20
PMC_BUSMODEN<2>: PMCJN2.11 U15.J21
PMC_BUSMODEN<3>: PMCJN2.14 U15.K21
PMC_BUSMODEN<4>: PMCJN2.16 U15.L21
PMC_C_BEN<0>: PMCJN1.52 U15.J23
PMC_C_BEN<1>: PMCJN2.43 U15.G24
PMC_C_BEN<2>: PMCJN2.32 U15.B25
PMC_C_BEN<3>: PMCJN1.26 U15.A27
PMC_CLK: PMCJN1.13 R349.2
PMC_DEVSELN: PMCJN1.37 R67.1 U15.B24
PMC_FRAMEN: PMCJN1.33 U15.C25
PMC_GNTN: PMCJN1.16 U15.B20
PMC_INTAN: PMCJN1.4 R80.1 U15.A29
PMC_INTBN: PMCJN1.5 R65.1 U15.K18
PMC_INTCN: PMCJN1.6 R81.1 U15.F19
PMC_INTDN: PMCJN1.9 R66.1 U15.F20
PMC_IRDYN: PMCJN1.36 R83.1 U15.D25
PMC_LOCKN: PMCJN1.40 R85.1 U15.H19
PMC_M66EN: PMCJN2.47 U15.H20
PMC_PAR: PMCJN1.43 U15.E24
PMC_PERRN: PMCJN2.39 R84.1 U15.D24
PMC_REQN: PMCJN1.17 U15.A20
PMC_RESETN: PMCJN2.13 U15.C19 U15.D19
PMC_SERRN: PMCJN2.42 R100.1 U15.B23
PMC_STOPN: PMCJN2.38 R99.1 U15.C24
PMC_TRDYN: PMCJN2.35 R82.1 U15.A24
PORSEL: R286.1 U15.AG15
PS_CDONE_N: J85.3
PS_CONFIG_N: J85.5 U19.4
PS_DCLK: J85.1 U19.2
PS_EPLD_D0: J85.9 U19.6 U19.7
PS_STATUS_N: J85.7 U19.5 U19.8
PWR_SW: R207.1 R216.2
Q_CF_ATASEL_N: CON3.9 U52.18
Q_CF_CS_N: CON3.32 U52.14
Q_CF_POWER: U52.22 U59.5
Q_CF_PRESENT_N: CON3.26 R318.2 U52.15
Q_CF_REG: CON3.44 U52.20
Q_CF_RESET_N: CON3.41 R319.2 U52.17
Q_SCRUZ_IO<0>: CON3.6 J92.3 U24.22
Q_SCRUZ_IO<1>: CON3.47 J92.4 U24.21
Q_SCRUZ_IO<2>: CON3.5 J92.5 U24.20
Q_SCRUZ_IO<3>: CON3.48 J92.6 U24.19
Q_SCRUZ_IO<4>: CON3.4 J92.7 U24.18
Q_SCRUZ_IO<5>: CON3.49 J92.8 U24.17
Q_SCRUZ_IO<6>: CON3.3 J92.9 U24.16
Q_SCRUZ_IO<7>: CON3.27 J92.10 U24.15
Q_SCRUZ_IO<8>: CON3.2 J92.11 U24.14
Q_SCRUZ_IO<9>: CON3.28 J92.12 U24.13
Q_SCRUZ_IO<10>: CON3.23 J92.13 U23.22
Q_SCRUZ_IO<11>: CON3.29 J92.14 U23.21
Q_SCRUZ_IO<12>: CON3.22 J92.15 U23.20
Q_SCRUZ_IO<13>: CON3.30 J92.16 U23.19
Q_SCRUZ_IO<14>: CON3.21 J92.17 U23.18
Q_SCRUZ_IO<15>: CON3.31 J92.18 U23.17
Q_SCRUZ_IO<16>: J92.21 R306.1 U23.16
Q_SCRUZ_IO<17>: CON3.35 J92.23 U23.15
Q_SCRUZ_IO<18>: CON3.34 J92.25 U23.14
Q_SCRUZ_IO<19>: CON3.42 J92.27 R305.1 U23.13
Q_SCRUZ_IO<20>: J92.28 U22.22
Q_SCRUZ_IO<21>: J92.29 U22.21
Q_SCRUZ_IO<22>: CON3.37 J92.31 R304.1 R307.1 U22.20
Q_SCRUZ_IO<23>: CON3.24 J92.32 R303.1 U22.19
Q_SCRUZ_IO<24>: CON3.19 J92.33 U22.18
Q_SCRUZ_IO<25>: CON3.20 J92.35 U22.17
Q_SCRUZ_IO<26>: CON3.18 J92.36 U22.16
Q_SCRUZ_IO<27>: CON3.7 J92.37 U22.15
Q_SCRUZ_IO<28>: CON3.45 J92.39 U22.14
Q_SCRUZ_IO<29>: CON3.8 J79.4 U22.13
Q_SCRUZ_IO<30>: CON3.46 J79.5 U39.22
Q_SCRUZ_IO<31>: CON3.10 J79.6 U39.21
Q_SCRUZ_IO<32>: CON3.11 J79.7 U39.20
Q_SCRUZ_IO<33>: CON3.12 J79.8 U39.19
Q_SCRUZ_IO<34>: CON3.14 J79.9 U39.18
Q_SCRUZ_IO<35>: CON3.15 J79.10 U39.17
Q_SCRUZ_IO<36>: CON3.16 J79.11 U39.16
Q_SCRUZ_IO<37>: CON3.17 J79.12 U39.15
Q_SCRUZ_IO<38>: CON3.36(WE_HSH_) J79.13 U39.14
Q_SCRUZ_IO<39>: CON3.43 J79.14 U39.13
RDN8: R132.1 U15.AC20
RDN_4: U7.AG24
REFCLKB14N: R342.1
REFCLKB14P: R342.2
REFCLKB15N: R343.1
REFCLKB15P: R343.2
RUNLU: J90.2 U21.5 U21.9
RUP8: R131.1 U15.AH19
RUP_4: U7.AG23
S_A_A: RN34.1 U26.12
S_A_B: RN33.1 U26.23
S_ALERTN: U12.11 U15.H14
S_B_A: RN34.2 U26.11
S_B_B: RN33.2 U26.22
S_C_A: RN34.3 U26.9
S_C_B: RN33.3 U26.20
S_CDONE_BUF_N: R133.1 R178.2 U15.G18 U19.27 U19.31
S_CDONE_N: U19.9
S_CONFIG_BUF_N: R123.1 U15.J18
S_D_A: RN34.4 U26.8
S_D_B: RN33.4 U26.19
S_DATA0: U15.E14 U19.24 U19.33
S_DATA1: U15.F14 U19.23
S_DATA2: U15.F15 U19.22
S_DATA3: U15.C16 U19.21
S_DATA4: U15.G19 U20.38
S_DATA5: U15.J19 U20.37
S_DATA6: U15.K19 U20.36
S_DATA7: U15.J20 U20.35
S_DCLK_BUF: R55.1 U15.E19 U19.28 U19.38
S_DEV_CLR_LED: RN22.2 U34.20
S_DIG_1_A: RN17.16 U15.AH18 U26.37
S_DIG_1_B: RN17.15 U15.AJ18 U26.38
S_DIG_1_C: RN17.14 U15.AD19 U26.40
S_DIG_1_D: RN17.13 U15.AE20 U26.41
S_DIG_1_DP: RN17.9(2) U15.AB19 U26.47
S_DIG_1_E: RN17.12 U15.AG20 U26.43
S_DIG_1_F: RN17.11 U15.AG21 U26.44
S_DIG_1_G: RN17.10 U15.AD20 U26.46
S_DIG_2_A: RN18.16 U15.AD21 U26.26
S_DIG_2_B: RN18.15 U15.AG23 U26.27
S_DIG_2_C: RN18.14 U15.AC21 U26.29
S_DIG_2_D: RN18.13 U15.AF22 U26.30
S_DIG_2_DP: RN18.9(2) U15.AK18 U26.36
S_DIG_2_E: RN18.12 U15.AD22 U26.32
S_DIG_2_F: RN18.11 U15.AB21 U26.33
S_DIG_2_G: RN18.10 U15.AA21 U26.35
S_DIP<0>: RN37.10 U15.AC23
S_DIP<1>: RN38.16 U15.AD24
S_DIP<2>: RN38.14 U15.AD23
S_DIP<3>: RN38.12 U15.AG24
S_DIP<4>: RN38.10 U15.AE24
S_DIP<5>: RN38.9(2) U15.AE23
S_DIP<6>: RN39.16 U15.AF24
S_DIP<7>: RN39.15 U15.AC22
S_DP_A: RN34.8 U26.2
S_DP_B: RN33.8 U26.13
S_E_A: RN34.5 U26.6
S_E_B: RN33.5 U26.17
S_EPC16_CEN: U15.V23 U29.78
S_EPC16_OEN: U15.Y26 U29.80
S_EPC16_RPN: U15.W28 U29.39 U29.72
S_EPC16_WEN: U15.V24 U29.33 U29.38
S_F_A: RN34.6 U26.5
S_F_B: RN33.6 U26.16
S_G_A: RN34.7 U26.3
S_G_B: RN33.7 U26.14
S_HEADER<0>: J68.1 U15.AA29
S_HEADER<1>: J68.3 U15.AA28
S_HEADER<2>: J68.5 U15.AB30
S_HEADER<3>: J68.7 U15.AB31
S_HEADER<4>: J68.9 U15.AA30
S_HEADER<5>: J68.11 U15.AA31
S_HEADER<6>: J68.13 U15.Y29
S_HEADER<7>: J68.15 U15.Y30
S_HEADER<8>: J68.17 U15.Y31
S_HEADER<9>: J68.19 U15.Y32
S_HEADER<10>: J68.20 U15.W29
S_HEADER<11>: J68.18 U15.W30
S_HEADER<12>: J68.16 U15.W31
S_HEADER<13>: J68.14 U15.W32
S_HEADER<14>: J68.12 U15.V29
S_HEADER<15>: J68.10 U15.V30
S_HEADER<16>: J68.8 U15.V31
S_HEADER<17>: J68.6 U15.V32
S_HEADER<18>: J68.4 U15.Y23
S_HEADER<19>: J68.2 U15.Y25
S_LED<0>: RN19.9(2) U15.AB22 U34.47
S_LED<1>: RN19.10 U15.AF23 U34.46
S_LED<2>: RN19.11 U15.AM29 U34.44
S_LED<3>: RN19.12 U15.AL29 U34.43
S_LED<4>: RN19.13 U15.AL30 U34.41
S_LED<5>: RN19.14 U15.AK29 U34.40
S_MICTOR_EP_<0>: J75.37 U15.AL20
S_MICTOR_EP_<1>: J75.35 U15.AK20
S_MICTOR_EP_<2>: J75.33 U15.AH20
S_MICTOR_EP_<3>: J75.31 U15.AL21
S_MICTOR_EP_<4>: J75.29 U15.AK21
S_MICTOR_EP_<5>: J75.27 U15.AJ21
S_MICTOR_EP_<6>: J75.25 U15.AM22
S_MICTOR_EP_<7>: J75.23 U15.AJ20
S_MICTOR_EP_<8>: J75.21 U15.AL22
S_MICTOR_EP_<9>: J75.19 U15.AK22
S_MICTOR_EP_<10>: J75.17 U15.AL23
S_MICTOR_EP_<11>: J75.15 U15.AK23
S_MICTOR_EP_<12>: J75.13 U15.AM24
S_MICTOR_EP_<13>: J75.11 U15.AH22
S_MICTOR_EP_<14>: J75.9 U15.AL24
S_MICTOR_EP_<15>: J75.7 U15.AJ23
S_MICTOR_EP_CLK: J75.5 U15.AM20
S_MICTOR_OP_<0>: J75.38 U15.AM26
S_MICTOR_OP_<1>: J75.36 U15.AM25
S_MICTOR_OP_<2>: J75.34 U15.AK24
S_MICTOR_OP_<3>: J75.32 U15.AL25
S_MICTOR_OP_<4>: J75.30 U15.AK25
S_MICTOR_OP_<5>: J75.28 U15.AJ25
S_MICTOR_OP_<6>: J75.26 U15.AL28
S_MICTOR_OP_<7>: J75.24 U15.AJ27
S_MICTOR_OP_<8>: J75.22 U15.AJ24
S_MICTOR_OP_<9>: J75.20 U15.AH24
S_MICTOR_OP_<10>: J75.18 U15.AL26
S_MICTOR_OP_<11>: J75.16 U15.AK26
S_MICTOR_OP_<12>: J75.14 U15.AM28
S_MICTOR_OP_<13>: J75.12 U15.AM27
S_MICTOR_OP_<14>: J75.10 U15.AJ26
S_MICTOR_OP_<15>: J75.8 U15.AK27
S_MICTOR_OP_CLK: J75.6 U15.AJ22
S_OVERTEMPN: U12.9 U15.B14
S_PB0_IN: C654.1 R180.2 RN14.11 U43.3
S_PB1_IN: C651.1 R181.2 RN14.9(2) U43.12
S_PB2_IN: C645.1 R182.2 RN37.16 U43.5
S_PB3_IN: C644.1 R183.2 RN37.15 U43.10
S_PB<0>: R180.1 U15.AB20 U43.13
S_PB<1>: R181.1 U15.AG22 U43.4
S_PB<2>: R182.1 U15.AB24 U43.11
S_PB<3>: R183.1 U15.AC24 U43.6
S_PB_DEV_CLR_N: R171.1 U15.AH14 U34.29 U43.2
S_PB_DEV_CLR_N_IN: C656.1 R171.2 RN14.13 U43.14
S_PGM0: U15.AD18 U21.2
S_PGM1: U15.AG14 U21.3
S_PGM2: U15.AA20 U21.4
S_PLL_ENA: R119.1 U15.AF19
S_RS232_CTS: R169.2 U15.Y28 U33.9
S_RS232_RTS: R170.2 U15.W23 U33.10
S_RS232_RXD: U15.Y27 U33.12
S_RS232_TXD: U15.W24 U33.11
S_RUNLU: R148.1 U15.AF14 U20.25 U21.35
S_RX1IN1: J124.3 U33.13
S_RX2IN1: J124.7 U33.8
S_SMB_CLK: U12.14 U15.J15
S_SMB_DATA: U12.12 U15.J14
S_STATUS_BUF_N: R158.1 U15.G16 U19.25 U19.32
S_TDI1: U15.D16
S_TDO1_SW: U15.F16
S_TEMPDIODEN: U12.4 U15.E18
S_TEMPDIODEP: U12.3 U15.F18
S_TX1OUT1: J124.2 U33.14
S_TX2OUT1: J124.8 U33.7
S_USER_LED1: RN21.8 U34.2
S_USER_LED2: RN21.7 U34.3
S_USER_LED3: RN21.6 U34.5
S_USER_LED4: RN21.5 U34.6
S_USER_LED5: RN21.4 U34.8
S_USER_LED6: RN21.3 U34.9
S_VCCSEL: R120.1 U15.AJ14
SCRUZ_CARDSELN: J92.38 R134.1 U15.B3 U22.23 U23.23 U24.23 U39.23 U52.23
SCRUZ_CLK_OSC_A: J78.9 R261.2 U15.AJ17
SCRUZ_IO<0>: U15.A11 U24.2
SCRUZ_IO<1>: U15.B12 U24.3
SCRUZ_IO<2>: U15.C12 U24.4
SCRUZ_IO<3>: U15.C13 U24.5
SCRUZ_IO<4>: U15.D13 U24.6
SCRUZ_IO<5>: U15.E13 U24.7
SCRUZ_IO<6>: U15.A13 U24.8
SCRUZ_IO<7>: U15.B13 U24.9
SCRUZ_IO<8>: U15.D12 U24.10
SCRUZ_IO<9>: U15.E11 U24.11
SCRUZ_IO<10>: U15.B9 U23.2
SCRUZ_IO<11>: U15.D10 U23.3
SCRUZ_IO<12>: U15.C10 U23.4
SCRUZ_IO<13>: U15.A9 U23.5
SCRUZ_IO<14>: U15.B11 U23.6
SCRUZ_IO<15>: U15.C11 U23.7
SCRUZ_IO<16>: U15.B10 U23.8
SCRUZ_IO<17>: U15.D11 U23.9
SCRUZ_IO<18>: U15.B7 U23.10
SCRUZ_IO<19>: U15.D8 U23.11
SCRUZ_IO<20>: U15.B8 U22.2
SCRUZ_IO<21>: U15.E9 U22.3
SCRUZ_IO<22>: U15.A8 U22.4
SCRUZ_IO<23>: U15.C9 U22.5
SCRUZ_IO<24>: U15.C8 U22.6
SCRUZ_IO<25>: U15.D9 U22.7
SCRUZ_IO<26>: U15.A7 U22.8
SCRUZ_IO<27>: U15.D6 U22.9
SCRUZ_IO<28>: U15.C6 U22.10
SCRUZ_IO<29>: U15.B5 U22.11
SCRUZ_IO<30>: U15.C7 U39.2
SCRUZ_IO<31>: U15.A5 U39.3
SCRUZ_IO<32>: U15.D7 U39.4
SCRUZ_IO<33>: U15.A6 U39.5
SCRUZ_IO<34>: U15.B6 U39.6
SCRUZ_IO<35>: U15.E7 U39.7
SCRUZ_IO<36>: U15.D5 U39.8
SCRUZ_IO<37>: U15.C3 U39.9
SCRUZ_IO<38>: U15.E5 U39.10
SCRUZ_IO<39>: U15.C4 U39.11
SCRUZ_SYS_RESETN: J92.1 U15.C5
SFP0_MOD_DEF4_<0>: J54.6 R226.2 U7.AG22
SFP0_MOD_DEF4_<1>: J54.5 R227.2 U7.AG20
SFP0_MOD_DEF4_<2>: J54.4 R228.2 U7.AG19
SFP0_RATE_SELECT4: J54.7 U7.AG18
SFP0_RX_LOS4: J54.8 R224.2 U7.AF22
SFP0_TX_DISABLE4: J54.3 R174.2 U7.AG17
SFP0_TX_FAULT4: J54.2 R229.2 U7.AF23
SFP1_MOD_DEF5_<0>: J64.6 R235.2 U7.AF20
SFP1_MOD_DEF5_<1>: J64.5 R237.2 U7.AF19
SFP1_MOD_DEF5_<2>: J64.4 R239.2 U7.AE23
SFP1_RATE_SELECT5: J64.7 U7.AE22
SFP1_RX_LOS5: J64.8 R230.2 U7.AE19
SFP1_TX_DISABLE5: J64.3 R173.2 U7.AE21
SFP1_TX_FAULT5: J64.2 R241.2 U7.AE20
SFP2_MOD_DEF6_<0>: J45.6 R218.2 U7.AD22
SFP2_MOD_DEF6_<1>: J45.5 R219.2 U7.AD21
SFP2_MOD_DEF6_<2>: J45.4 R220.2 U7.AD20
SFP2_RATE_SELECT6: J45.7 U7.AD19
SFP2_RX_LOS6: J45.8 R217.2 U7.AC21
SFP2_TX_DISABLE6: J45.3 R162.2 U7.AD18
SFP2_TX_FAULT6: J45.2 R221.2 U7.AC22
SFP3_MOD_DEF7_<0>: J38.6 R206.2 U7.AC19
SFP3_MOD_DEF7_<1>: J38.5 R209.2 U7.AC18
SFP3_MOD_DEF7_<2>: J38.4 R210.2 U7.AC17
SFP3_RATE_SELECT7: J38.7 U7.AB21
SFP3_RX_LOS7: J38.8 R205.2 U7.AB18
SFP3_TX_DISABLE7: J38.3 R161.2 U7.AB20
SFP3_TX_FAULT7: J38.2 R211.2 U7.AB19
SFP_VCCR1_4: C60.1 C430.1 J54.15
SFP_VCCR1_5: C77.1 C464.1 J64.15
SFP_VCCR1_6: C52.1 C352.1 J45.15
SFP_VCCR1_7: C50.1 C282.1 J38.15
SFP_VCCT1_4: C433.1 J54.16
SFP_VCCT1_5: C493.1 J64.16
SFP_VCCT1_6: C363.1 J45.16
SFP_VCCT1_7: C297.1 J38.16
SMA_INPUT1_TO_SGX_N: J60.1(OUTPUT) R322.2
SMA_INPUT1_TO_SGX_P: J52.1(OUTPUT) R322.1
SMA_INPUT2_TO_SGX_N: J16.1(OUTPUT)
SMA_INPUT2_TO_SGX_P: J24.1(OUTPUT)
SMA_INPUT3_TO_SGX_N: J121.1(OUTPUT)
SMA_INPUT3_TO_SGX_P: J122.1(OUTPUT)
SMA_INPUT4_TO_SGX_N: J123.2(4) U7.AA4
SMA_INPUT4_TO_SGX_P: J123.1 U7.AA3
SPGM0: R292.1 U20.28 U21.38 U29.14
SPGM1: R293.1 U20.27 U21.37 U29.13
SPGM2: R294.1 U20.26 U21.36 U29.15
STX_PMC_CLK: U15.A19 U15.AJ16
STX_PMC_GNTN: U15.C21 U15.C30
STX_PMC_REQN: U15.B21 U15.B30
TCK: J87.1 R56.1 U15.G14 U29.35 U30.35
TDI1: J87.9 R160.1
TDO: J87.3 U30.44
TDO1_EPC16: U29.44 U30.42
TEMPDIODEN: U7.B3
TEMPDIODEP: U7.G9
TMS: J87.5 R41.1 U15.E15 U29.48 U30.48
TP10: U7.AE10
TP11: U7.AF12
TP12: U7.AB11
TP13: U7.AG11
TP17: U7.AF10
TP21: U15.V27
TP22: U15.V28
TP23: U15.W27
TP24: U15.W26
TP25: U15.W25
TP29: U15.AE15
TP69: R358.2 U29.37
TP70: R359.2 U30.37
TRIG_155_52_N: R347.2 U18.11 U47.3
TRIG_155_52_P: R347.1 U18.12 U47.2
TRIG_156_25: J97.1(OUTPUT) U46.7
TRIG_156_25_N: R346.2 U32.11 U46.3
TRIG_156_25_P: R346.1 U32.12 U46.2
TRSTN: R44.1 U15.G15
VEND_SPECIFIC0: R333.1 R334.2 R341.2 U27.11
VEND_SPECIFIC1: R332.1 R335.2 R340.2 U27.15
VEND_SPECIFIC2: R331.1 R336.2 R339.2 U27.16
VEND_SPECIFIC3: R330.1 R337.2 R338.2 U27.24(VEND3)
VREF_DIMM: XU2.1
XCVR_RX_N0C: C115.1 J98.1(OUTPUT)
XCVR_RX_N1C: C101.1 J81.1(OUTPUT)
XCVR_RX_N2C: C25.1 J27.1(OUTPUT)
XCVR_RX_N3C: C24.1 J26.1(OUTPUT)
XCVR_RX_N8C: C1.1 J1.6A
XCVR_RX_N9C: C3.1 J1.6C
XCVR_RX_N10C: C5.1 J1.6E
XCVR_RX_N11C: C7.1 J1.6G
XCVR_RX_N16C: C22.1 J23.2
XCVR_RX_N17C: C29.1 J32.2
XCVR_RX_N18C: C17.1 J15.2
XCVR_RX_N19C: C10.1 J11.2
XCVR_RX_N<0>: C115.2 U7.M4
XCVR_RX_N<1>: C101.2 U7.M2
XCVR_RX_N<2>: C25.2 U7.L4
XCVR_RX_N<3>: C24.2 U7.L2
XCVR_RX_N<4>: J54.12 U7.R3
XCVR_RX_N<5>: J64.12 U7.N5
XCVR_RX_N<6>: J45.12 U7.N3
XCVR_RX_N<7>: J38.12 U7.P2
XCVR_RX_N<8>: C1.2 U7.K4
XCVR_RX_N<9>: C3.2 U7.K2
XCVR_RX_N<10>: C5.2 U7.J4
XCVR_RX_N<11>: C7.2 U7.J2
XCVR_RX_N<12>: U7.H2 U27.42
XCVR_RX_N<13>: U7.G4 U27.45
XCVR_RX_N<14>: U7.G2 U27.48
XCVR_RX_N<15>: U7.F4 U27.51
XCVR_RX_N<16>: C22.2 U7.F2
XCVR_RX_N<17>: C29.2 U7.E4
XCVR_RX_N<18>: C17.2 U7.E2
XCVR_RX_N<19>: C10.2 U7.D2
XCVR_RX_P0C: C105.1 J93.1(OUTPUT)
XCVR_RX_P1C: C104.1 J86.1(OUTPUT)
XCVR_RX_P2C: C20.1 J19.1(OUTPUT)
XCVR_RX_P3C: C21.1 J18.1(OUTPUT)
XCVR_RX_P8C: C2.1 J1.6B
XCVR_RX_P9C: C4.1 J1.6D
XCVR_RX_P10C: C6.1 J1.6F
XCVR_RX_P11C: C8.1 J1.6H
XCVR_RX_P16C: C23.1 J23.3
XCVR_RX_P17C: C32.1 J32.3
XCVR_RX_P18C: C18.1 J15.3
XCVR_RX_P19C: C11.1 J11.3
XCVR_RX_P<0>: C105.2 U7.M3
XCVR_RX_P<1>: C104.2 U7.M1
XCVR_RX_P<2>: C20.2 U7.L3
XCVR_RX_P<3>: C21.2 U7.L1
XCVR_RX_P<4>: J54.13 U7.R2
XCVR_RX_P<5>: J64.13 U7.N4
XCVR_RX_P<6>: J45.13 U7.N2
XCVR_RX_P<7>: J38.13 U7.P1
XCVR_RX_P<8>: C2.2 U7.K3
XCVR_RX_P<9>: C4.2 U7.K1
XCVR_RX_P<10>: C6.2 U7.J3
XCVR_RX_P<11>: C8.2 U7.J1
XCVR_RX_P<12>: U7.H1 U27.41
XCVR_RX_P<13>: U7.G3 U27.44
XCVR_RX_P<14>: U7.G1 U27.47
XCVR_RX_P<15>: U7.F3 U27.50
XCVR_RX_P<16>: C23.2 U7.F1
XCVR_RX_P<17>: C32.2 U7.E3
XCVR_RX_P<18>: C18.2 U7.E1
XCVR_RX_P<19>: C11.2 U7.D1
XCVR_TX_N<0>: J77.1(OUTPUT) U7.R7
XCVR_TX_N<1>: J105.1(OUTPUT) U7.R5
XCVR_TX_N<2>: J28.1(OUTPUT) U7.R11
XCVR_TX_N<3>: J25.1(OUTPUT) U7.P9
XCVR_TX_N<4>: J54.19 U7.L9
XCVR_TX_N<5>: J64.19 U7.J9
XCVR_TX_N<6>: J45.19 U7.T6
XCVR_TX_N<7>: J38.19 U7.T10
XCVR_TX_N<8>: J1.5B U7.P7
XCVR_TX_N<9>: J1.5D U7.P5
XCVR_TX_N<10>: J1.5F U7.P11
XCVR_TX_N<11>: J1.5H U7.N9
XCVR_TX_N<12>: U7.N7 U27.56
XCVR_TX_N<13>: U7.M9 U27.59
XCVR_TX_N<14>: U7.M7 U27.62
XCVR_TX_N<15>: U7.M11 U27.65
XCVR_TX_N<16>: J23.6 U7.L8
XCVR_TX_N<17>: J32.6 U7.L6
XCVR_TX_N<18>: J15.6 U7.K9
XCVR_TX_N<19>: J11.6 U7.K7
XCVR_TX_P<0>: J72.1(OUTPUT) U7.R6
XCVR_TX_P<1>: J101.1(OUTPUT) U7.R4
XCVR_TX_P<2>: J20.1(OUTPUT) U7.R10
XCVR_TX_P<3>: J17.1(OUTPUT) U7.P8
XCVR_TX_P<4>: J54.18 U7.L10
XCVR_TX_P<5>: J64.18 U7.J8
XCVR_TX_P<6>: J45.18 U7.T5
XCVR_TX_P<7>: J38.18 U7.T11
XCVR_TX_P<8>: J1.5A U7.P6
XCVR_TX_P<9>: J1.5C U7.P4
XCVR_TX_P<10>: J1.5E U7.P10
XCVR_TX_P<11>: J1.5G U7.N8
XCVR_TX_P<12>: U7.N6 U27.55
XCVR_TX_P<13>: U7.M8 U27.58
XCVR_TX_P<14>: U7.M6 U27.61
XCVR_TX_P<15>: U7.M10 U27.64
XCVR_TX_P<16>: J23.5(TX_P) U7.L7
XCVR_TX_P<17>: J32.5(TX_P) U7.L5
XCVR_TX_P<18>: J15.5(TX_P) U7.K8
XCVR_TX_P<19>: J11.5(TX_P) U7.K6
XPAK_LASI: R105.2 R258.1 U7.AG14 U27.9
XPAK_MDC: J63.5 R109.2 R254.1 U27.18
XPAK_MDIN: J63.9 R101.1
XPAK_MDIO: J63.7 R101.2 R108.2 R255.1 U27.17
XPAK_MOD_DET: R122.2 U7.AG15 U27.14
XPAK_PRTAD<0>: R114.2 R249.1 U7.AG10 U27.23
XPAK_PRTAD<1>: R113.2 R250.1 U7.AH16 U27.22
XPAK_PRTAD<2>: R112.2 R251.1 U7.AH7 U27.21
XPAK_PRTAD<3>: R111.2 R252.1 U7.AH6 U27.20
XPAK_PRTAD<4>: R110.2 R253.1 U7.AH9 U27.19
XPAK_TX_ON: R107.2 R256.1 U7.AG12 U27.12
XPAK_VEND<0>: R334.1 U7.AH8
XPAK_VEND<1>: R335.1 U7.AH11
XPAK_VEND<2>: R336.1 U7.AG9
XPAK_VEND<3>: R337.1 U7.AG8
XPAK_X_RST: R106.2 R257.1 U7.AG13 U27.10
XTAL1_SGX_INT_N: C107.1 R167.2 U32.19
XTAL1_SGX_INT_P: C106.1 R167.1 U32.20
XTAL1_SGX_N: C107.2 R16.2 R195.2
XTAL1_SGX_P: C106.2 R15.2 R196.1
XTAL1_STX_INT_N: C109.1 R168.2 U32.16
XTAL1_STX_INT_P: C108.1 R168.1 U32.17
XTAL1_STX_N: C109.2 R87.2 R88.2 U15.T30
XTAL1_STX_P: C108.2 R89.2 R90.2 U15.T29
XTAL1_TP_N: R165.2 U32.14
XTAL1_TP_P: R165.1 U32.15
XTAL2_SGX_INT_N: C97.1 R137.2 U18.19
XTAL2_SGX_INT_P: C96.1 R137.1 U18.20
XTAL2_SGX_N: C97.2 R191.2 R192.2
XTAL2_SGX_P: C96.2 R193.2 R194.2
XTAL2_STX_INT_N: C99.1 R138.2 U18.16
XTAL2_STX_INT_P: C98.1 R138.1 U18.17
XTAL2_STX_N: C99.2 R91.2 R92.2 U15.T28
XTAL2_STX_P: C98.2 R93.2 R94.2 U15.T27
XTAL2_TP_N: R135.2 U18.14
XTAL2_TP_P: R135.1 U18.15
XTAL3_OUT_SGX: R345.1 U13.6
XTAL3_OUT_SGX_N: R345.2 R348.2
XTAL3_OUT_STX: U13.5 U15.AK19
XTAL3_OUT_TP1: J69.1(OUTPUT) U13.7
XTAL3_OUT_TP2: U13.8
N16695485: J124.1 J124.4 J124.6
N16771186: R116.1 R118.1 U11.18
N16771204: C94.1 R129.2 RJ1.13 RJ1.14
N16771208: C94.2 RJ1.8
N16771572: R103.1 R104.1 U11.17
N16771620: C83.2 R104.2 R116.2
N16771734: R259.1 U11.20
N16827057: R264.2 U26.48
N16827063: R263.2 U26.24
N16827184: R265.2 U26.1
N16827202: R262.2 U26.25
N16873824: R266.2 U25.25
N16874052: R267.2 U25.24
N16874056: R268.2 U25.48
N16874162: R269.2 U25.1
N16874692: RN36.16
N16874694: RN36.15
N16874698: RN36.14
N16874700: RN36.13
N16874702: RN36.12
N16874704: RN36.11
N16874706: RN36.10
N16874715: RN36.9(2)
N16874738: RN35.16
N16874740: RN35.15
N16874745: RN35.14
N16874747: RN35.13
N16874749: RN35.12
N16874754: RN35.11
N16874756: RN35.10
N16874758: RN35.9(2)
N17102164: RN33.16
N17102165: RN33.15
N17102167: RN33.14
N17102168: RN33.13
N17102169: RN33.12
N17102171: RN33.11
N17102172: RN33.10
N17102173: RN33.9(2)
N17102479: RN34.15
N17102484: RN34.9(2)
N17102491: RN34.12
N17102495: RN34.13
N17102503: RN34.16
N17102508: RN34.11
N17102509: RN34.14
N18367160: U20.12
N18367161: U20.13
N18367162: U20.14
N18368499: U20.17
N18368500: U20.18
N18368501: U20.19
N18445704: R140.2 U30.66
N24962500: R297.1 R298.2 U42.5

Pads without a net: CON3 40; ISO1 3 4 5 6; J1 1A 1B 1C 1D 1E 1F 1G 1H 2A 2B 2C 2D 2E 2F 2G 2H 3A 3B 3C 3D 3E 3F 3G 3H 4A 4B 4C 4D 4E 4F 4G 4H 7A 7B 7C 7D 7E 7F 7G 7H 8A 8B 8C 8D 8E 8F 8G 8H 9A 9B 9C 9D 9E 9F 9G 9H 10A 10B 10C 10D 10E 10F 10G 10H; J4 4; J31 5 18; J34 1 2 3 4; J36 1 3 5 7; J57 A27 B27; J58 A27 B27; J63 1 3 6 8; J75 1 2 3 4; J78 3 15 17 19; J79 2 3; J85 8; J87 7 8; J92 20; J108 1BG 5B 8H; J109 1A 1B 1E 1F 1G 1H 2A 2B 2E 2F 2G 2H 3A 3B 3C 3D 3E 3F 3G 3H 4A 4B 4C 4D 4E 4F 4G 4H 5C 5D 5E 5F 5G 5H 6A 6B 6C 6D 6E 6F 6G 6H 7A 7B 7C 7D 7E 7F 7G 7H 8A 8B 8C 8D 8E 8F 9A 9B 9C 9D 9E 9F 10A 10B 10C 10D 10E 10F; J124 9 18; PMCJN1 1 10 42 64; PMCJN2 3 4 5 8 9 10 17 34 52 54 55 57 58 60 61 64; RJ1 5 7; RN20 1 2 8 9 15 16; RN22 8 9; RN27 8 9; RN39 3 4 5 6 7 8 9 10 11 12 13 14; U4 4; U5 5 13 16; U6 2 6 7 10 16 17 18 19; U7 A3 A15 A16 A17 A18 A19 A30 AA1 AA2 AA5 AA6 AA7 AA8 AA9 AA10 AA11 AA16 AA17 AA22 AA23 AA28 AA29 AA30 AA31 AA32 AB1 AB2 AB3 AB4 AB5 AB6 AB7 AB8 AB9 AB10 AB27 AB28 AC1 AC2 AC3 AC4 AC6 AC7 AC8 AC9 AC11 AC13 AC23 AC29 AC30 AD1 AD2 AD3 AD4 AD5 AD6 AD7 AD8 AD9 AD28 AD29 AD30 AE1 AE2 AE3 AE4 AE5 AE6 AE9 AE24 AF1 AF2 AF3 AF4 AF5 AF6 AF8 AF11 AF13 AF14 AF15 AF16 AF24 AF27 AF28 AG1 AG2 AG3 AG4 AG5 AG21 AG25 AG28 AH1 AH2 AH3 AH4 AH12 AH15 AH17 AH18 AH19 AH20 AH21 AJ1 AJ2 AJ3 AJ4 AJ9 AJ15 AJ16 AJ17 AJ18 AJ24 AJ29 AJ30 AK1 AK2 AK3 AK14 AK15 AK16 AK17 AK18 AK19 AK30 AK31 AK32 AL2 AL3 AL15 AL16 AL17 AL18 AL19 AL30 AL31 AM3 AM15 AM16 AM17 AM18 AM19 AM30 B2 B6 B9 B12 B16 B17 B18 B19 B22 B24 B26 B30 B31 C1 C2 C3 C5 C7 C11 C14 C17 C18 C19 C29 C30 C31 C32 D3 D4 D9 D17 D18 D20 D24 D29 D30 D31 D32 E9 E12 E14 E17 E18 E21 E29 E30 F5 F6 F12 F14 F16 F17 F18 F19 F20 F21 F24 F25 F28 G5 G6 G14 G19 G23 G24 G25 G27 G28 H3 H4 H5 H6 H9 H10 H12 H19 H20 H21 H23 H24 H27 H28 J5 J6 J7 J10 J12 J13 J15 J16 J17 J23 J25 J26 J27 J28 J29 J30 K11 K15 K16 K17 K24 K25 L12 L16 L17 L22 L27 L28 M5 M16 M17 M28 N10 N11 P3 P22 P23 P30 R1 R32 T1 T2 T3 T4 T12 T21 T29 T31 T32 U1 U2 U3 U4 U5 U6 U10 U11 U12 U21 U29 U30 U31 U32 V1 V2 V3 V4 V5 V6 V7 V9 V10 V32 W1 W2 W3 W4 W5 W6 W7 W8 W9 W10 W11 W22 W23 W30 Y4 Y5 Y6 Y7 Y8 Y9; U9 1 4 6; U10 1 10 12 14 16 21 23 28 30; U11 2 3 4 5 7 8 9 10 25 26 27 28 47 109 111 112 113 114 115 116 118 119 121 122 123 124 125 126 128; U12 5 13 16; U15 A4 A14 A16 A17 A18 A26 AA6 AA7 AA8 AA9 AA11 AA13 AA14 AA15 AA18 AA19 AA22 AB6 AB7 AB9 AB10 AB12 AB14 AB15 AB18 AB23 AC5 AC6 AC7 AC8 AC10 AC11 AC14 AC15 AC18 AC19 AD1 AD2 AD5 AD6 AD7 AD8 AD10 AD11 AD15 AE5 AE6 AE7 AE8 AE10 AE14 AE21 AE22 AF5 AF6 AF7 AF8 AF11 AF12 AF13 AF21 AG5 AG7 AG8 AG13 AG19 AG25 AG26 AG28 AH1 AH2 AH4 AH7 AH11 AH13 AH26 AH28 AH29 AH31 AH32 AJ9 AJ10 AJ11 AJ12 AJ13 AJ28 AJ29 AK5 AK8 AK9 AK10 AK11 AK12 AK13 AK14 AK16 AK17 AK28 AK30 AL8 AL9 AL10 AL11 AL12 AL13 AL14 AL27 AM9 AM11 AM13 AM14 AM16 AM18 B4 B16 B17 B18 C18 C20 D4 D14 D18 D20 D21 E1 E2 E4 E20 E29 E31 E32 F1 F2 F3 F4 F5 F7 F8 F9 F10 F11 F21 F22 F24 F25 F28 F29 F30 F31 F32 G1 G2 G3 G4 G7 G8 G9 G10 G11 G12 G13 G20 G21 G22 G25 G26 G27 G28 G29 H1 H2 H3 H4 H9 H10 H21 H27 H28 H31 J1 J2 J3 J4 J9 J10 J11 J13 J22 K2 K3 K4 K9 K10 K11 K14 K15 K20 K22 K29 L1 L2 L3 L9 L10 L11 L12 L13 L15 L18 L19 L22 M2 M3 M4 M5 M10 M11 M22 M23 M31 N1 N2 N3 N4 N11 N22 P1 P2 P3 P4 P7 P8 P11 P22 R1 R2 R3 R4 R7 R8 R11 R25 R26 T1 T2 T11 T31 T32 U5 U6 U22 U27 U28 V1 V2 V3 V4 V5 V6 V7 V8 V9 V10 V22 V25 V26 W5 W6 W7 W8 W9 W10 W11 W12 W21 W22 Y5 Y6 Y7 Y8 Y9 Y10 Y11 Y12 Y21 Y22; U18 5 7; U19 1 11; U20 1 11; U21 1 11; U22 1; U23 1; U24 1; U27 13 26 38 39 67 68; U29 3 4 7 18 19 20 24 30 57 63 64 74 76 77; U30 3 4 7 18 19 20 24 30 57 63 64 74 76 77; U32 5 7; U34 23; U39 1; U44 6 10; U45 6; U46 1 4; U47 1 4; U52 1 3 5 8 11 13 16 19 21; U53 1; XU2 6 15 19 27 36 45 46 55 68 83 92 102 104 113 126 135 147 156 165 203 212 224 233; Y4 2 5

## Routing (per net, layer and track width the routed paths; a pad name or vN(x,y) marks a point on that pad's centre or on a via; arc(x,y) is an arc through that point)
3.3V: length 13.3
  BOTTOM w0.508: 26.03,168.91 26.59,168.36 PMCJN1.41 ; PMCJN1.31 21.59,168.27 22.23,168.91 ; PMCJN1.57 34.59,168.57 34.92,168.91 ; PMCJN1.19 15.59,168.62 15.88,168.91 ; 28.58,168.91 28.59,168.9 PMCJN1.45
5VM: length 15.9
  BOTTOM w0.508: 14.61,160.02 14.59,160.04 PMCJN1.18 ; 9.52,160.02 9.59,160.08 PMCJN1.8 ; 19.69,160.02 20.59,160.92 PMCJN1.30 ; PMCJN1.62 36.59,160.41 36.2,160.02 ; PMCJN1.50 30.59,162.51 30.59,160.76 29.84,160.02 ; PMCJN1.38 24.59,160.2 24.77,160.02
12VM: length 130.4
  BOTTOM w0.635: 3.31,152.41 2.54,151.64 2.54,124.84 4.06,123.32 7.75,123.32 8.51,124.08 11.56,124.08 13.46,122.17 ; 3.31,152.41 PMCJN2.1 6.6,152.39 6.6,150.5 ; 3.31,152.41 3.31,169.93 2.92,170.32 2.92,175.89 3.31,176.28 3.31,199.14 8.38,204.22 27.69,204.22 35.56,212.09
-12VM: length 3.5
  BOTTOM w0.508: PMCJN1.2 6.59,162.51 6.59,164.2 6.86,164.47 8.25,164.47
GND_HSSI: length 7.7
  L14_GND3 w0.094: 241.81,122.68 241.94,122.81 ; 244.22,122.81 244.22,123.19 ; 252.98,126.16 252.91,126.24
  L14_GND3 w0.127: 256.79,211.07 257.56,210.31 257.89,210.31 ; 271.15,231.27 271.15,230.5 ; 229.74,230.63 229.23,230.12 ; 226.69,230.5 226.69,229.9 ; 221.36,230.5 221.36,230.12 221.61,229.87 ; 224.16,230.76 224.16,229.87 ; 255.27,224.41 255.27,224.28 254.89,223.9 ; 232.13,230.5 231.47,230.5 ; 227.71,231.39 227.33,231.01
GND_PLL: length 0.7
  L17_PWR3 w0.094: 221.87,204.47 222.38,204.47
  L17_PWR3 w0.635: 201.68,187.83 201.8,187.71
NET_9_I26_1: length 3.9
  BOTTOM w0.127: 8.25,146.05 6.98,146.05 6.59,146.45 6.59,148.51 PMCJN2.2
PMC_AD<0>: length 4
  BOTTOM w0.127: 36.2,170.18 36.7,169.67 36.7,168.53 36.59,168.42 PMCJN1.61
PMC_AD<1>: length 4.2
  BOTTOM w0.127: 36.2,158.75 35.43,159.51 35.43,162.38 35.56,162.51 PMCJN1.60
PMC_AD<2>: length 2.8
  BOTTOM w0.127: PMCJN1.59 35.59,168.3 36.2,168.91
PMC_AD<3>: length 2.6
  BOTTOM w0.127: PMCJN1.58 34.59,160.36 34.92,160.02
PMC_AD<4>: length 2.5
  BOTTOM w0.127: 33.66,168.91 33.59,168.84 PMCJN1.55
PMC_AD<9>: length 4.2
  BOTTOM w0.127: 31.12,170.18 30.35,169.42 30.35,168.2 30.59,167.96 PMCJN1.49
PMC_AD<11>: length 4.2
  BOTTOM w0.127: 29.84,158.75 29.15,159.45 29.15,160.34 29.59,160.78 29.59,162.51 PMCJN1.48
PMC_AD<13>: length 4.1
  BOTTOM w0.127: 28.58,144.78 29.08,145.29 29.08,146.69 28.72,147.05 28.72,147.07 28.59,147.19 28.59,148.51 PMCJN2.46
PMC_AD<15>: length 2.5
  BOTTOM w0.127: 28.58,160.02 28.59,160.03 28.59,162.51 PMCJN1.46
PMC_AD<19>: length 2.7
  BOTTOM w0.127: 20.95,168.91 20.59,168.54 PMCJN1.29
PMC_AD<20>: length 2.5
  BOTTOM w0.127: PMCJN2.28 19.59,148.51 19.59,146.15 19.69,146.05
PMC_AD<22>: length 2.5
  BOTTOM w0.127: PMCJN1.27 19.59,166.41 19.59,168.81 19.69,168.91
PMC_AD<29>: length 2.6
  BOTTOM w0.127: 15.88,146.05 15.59,146.34 PMCJN2.20
PMC_BUSMODEN<1>: length 4.3
  BOTTOM w0.127: PMCJN1.7 9.59,167.96 10.16,168.53 10.16,169.54 9.52,170.18
PMC_DEVSELN: length 2.8
  BOTTOM w0.127: PMCJN1.37 24.59,168.23 25.12,168.76 25.12,168.96
PMC_FRAMEN: length 4.1
  BOTTOM w0.127: PMCJN1.33 22.59,168.13 22.86,168.4 22.86,168.56 22.92,168.62 22.92,169.61 23.49,170.18
PMC_IRDYN: length 2.5
  BOTTOM w0.127: 23.49,160.02 23.59,160.11 PMCJN1.36
PMC_LOCKN: length 2.7
  BOTTOM w0.127: 26.03,160.02 25.59,160.47 PMCJN1.40

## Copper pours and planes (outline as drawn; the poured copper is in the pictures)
1.5V_A_INT on TOP (solid shape): 266.06,25.53 266.06,21.59 265.43,20.95 247.01,20.95 246.38,21.59 246.38,25.4 247.01,26.03 265.56,26.03
1.5V_A_INT on BOTTOM (solid shape): 250.19,41.91 250.82,41.27 250.82,41.24 253.97,41.24 255.91,43.18 263.53,43.18 264.16,42.55 264.16,38.73 263.53,38.1 259.72,38.1 258.44,36.83 258.44,22.23 255.27,19.05 255.27,15.24 254.63,14.61 245.11,14.61 244.47,15.24 244.47,19.05 241.3,22.23 241.3,40.64 241.9,41.24 248.89,41.24 249.56,41.91 249.56,45.09 250.19,45.09
1.5V_ENABLE on BOTTOM (solid shape): 157.48,202.82 157.48,201.55 156.84,200.91 151.13,200.91 150.5,201.55 150.5,202.95 151,203.45 156.84,203.45
1.5V_GX_INT on BOTTOM (solid shape): 99.06,290.83 99.06,285.75 97.79,284.48 90.8,284.48 89.53,285.75 89.53,288.93 88.9,289.56 87.12,289.56 86.49,290.2 86.49,291.47 87.12,292.1 97.79,292.1
1.5V_GX_INT on BOTTOM (solid shape): outline of 432 points within 234.57,132.72 266.06,142.88
1.5V_GX_INT on L6_IS3 (solid shape): outline of 1876 points within 249.56,102.87 269.24,143.51
1.5V_GX_INT on L11_PWR2 (solid shape): outline of 5925 points within 89.09,100.52 271.59,291.27
1.5V_OUT on TOP (solid shape): 101.6,300.99 101.6,295.28 100.96,294.64 100.96,288.29 101.6,287.66 114.3,287.66 114.93,288.29 114.93,294.64 114.3,295.28 114.3,300.99 114.93,301.62 118.74,301.62 119.38,300.99 119.38,293.37 116.84,290.83 116.84,286.39 114.93,284.48 100.33,284.48 98.42,286.39 98.42,291.47 96.52,293.37 96.52,300.99 97.16,301.62 100.96,301.62
1.5V_OUT on TOP (solid shape): 150.5,230.12 150.5,222.5 151.76,221.23 154.94,221.23 155.57,220.6 155.57,215.52 154.94,214.88 151.76,214.88 151.13,214.25 151.13,211.2 149.22,209.3 149.22,207.01 148.84,206.63 147.07,206.63 146.69,207.01 146.69,209.3 146.3,209.68 146.3,216.53 145.41,217.42 142.75,217.42 142.24,217.93 142.24,230.76 149.86,230.76
1.5V_OUT on L3_IS1 (solid shape): outline of 8333 points within 94.61,208.91 157.48,302.26
